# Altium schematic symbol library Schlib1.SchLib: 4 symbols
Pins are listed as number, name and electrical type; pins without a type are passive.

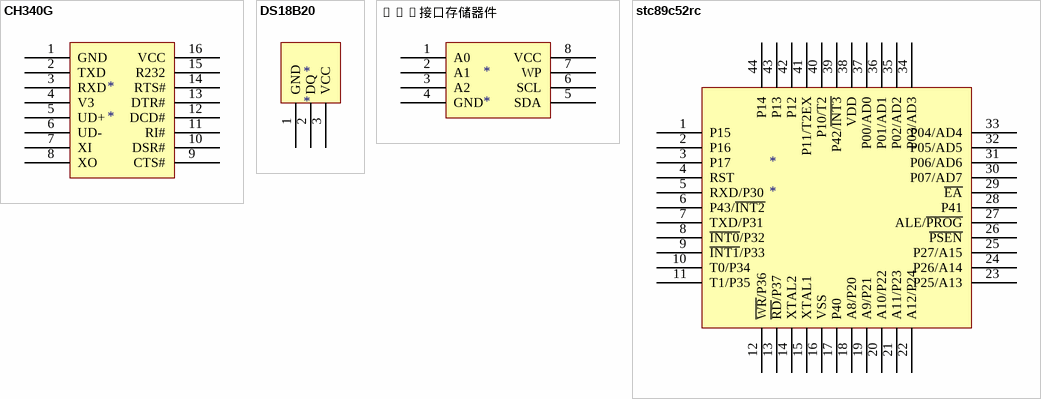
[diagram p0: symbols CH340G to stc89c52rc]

## CH340G
designator *
pins: 1 GND, 2 TXD, 3 RXD, 4 V3, 5 UD+, 6 UD-, 7 XI, 8 XO, 9 CTS#, 10 DSR#, 11 RI#, 12 DCD#, 13 DTR#, 14 RTS#, 15 R232, 16 VCC

## DS18B20
designator *
pins: 1 GND, 2 DQ, 3 VCC

## IIC接口存储器件
designator *
pins: 1 A0, 2 A1, 3 A2, 4 GND, 5 SDA, 6 SCL, 7 WP, 8 VCC

## stc89c52rc
designator *
pins: 1 P15, 2 P16, 3 P17, 4 RST, 5 RXD/P30, 6 P43/~{INT2}, 7 TXD/P31, 8 ~{INT0}/P32, 9 ~{INT1}/P33, 10 T0/P34, 11 T1/P35, 12 ~{WR}/P36, 13 ~{RD}/P37, 14 XTAL2, 15 XTAL1, 16 VSS, 17 P40, 18 A8/P20, 19 A9/P21, 20 A10/P22, 21 A11/P23, 22 A12/P24, 23 P25/A13, 24 P26/A14, 25 P27/A15, 26 ~{PSEN}, 27 ALE/~{PROG}, 28 P41, 29 ~{EA}, 30 P07/AD7, 31 P06/AD6, 32 P05/AD5, 33 P04/AD4, 34 P03/AD3, 35 P02/AD2, 36 P01/AD1, 37 P00/AD0, 38 VDD, 39 P42/~{INT3}, 40 P10/T2, 41 P11/T2EX, 42 P12, 43 P13, 44 P14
